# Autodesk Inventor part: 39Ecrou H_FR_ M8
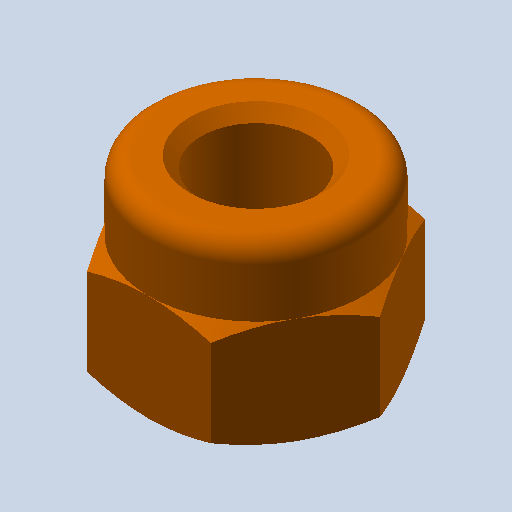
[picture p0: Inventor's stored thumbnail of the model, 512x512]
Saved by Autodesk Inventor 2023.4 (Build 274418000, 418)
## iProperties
Created: 2011-01
Part Number: 39Ecrou H_FR_ M8
Document SubType Name: Modeling
Designer: eric
Density: 1 g/cm^3
Mass: 1.10039 g
Surface Area: 8.5432 cm^2
Volume: 1.10039 cm^3
Material: Générique
Appearance: 255,128,0_1
Author: eric
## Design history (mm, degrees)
feature "Base1"
node "Corps solides"
node "Corps surfaciques"
node "Solide1"
